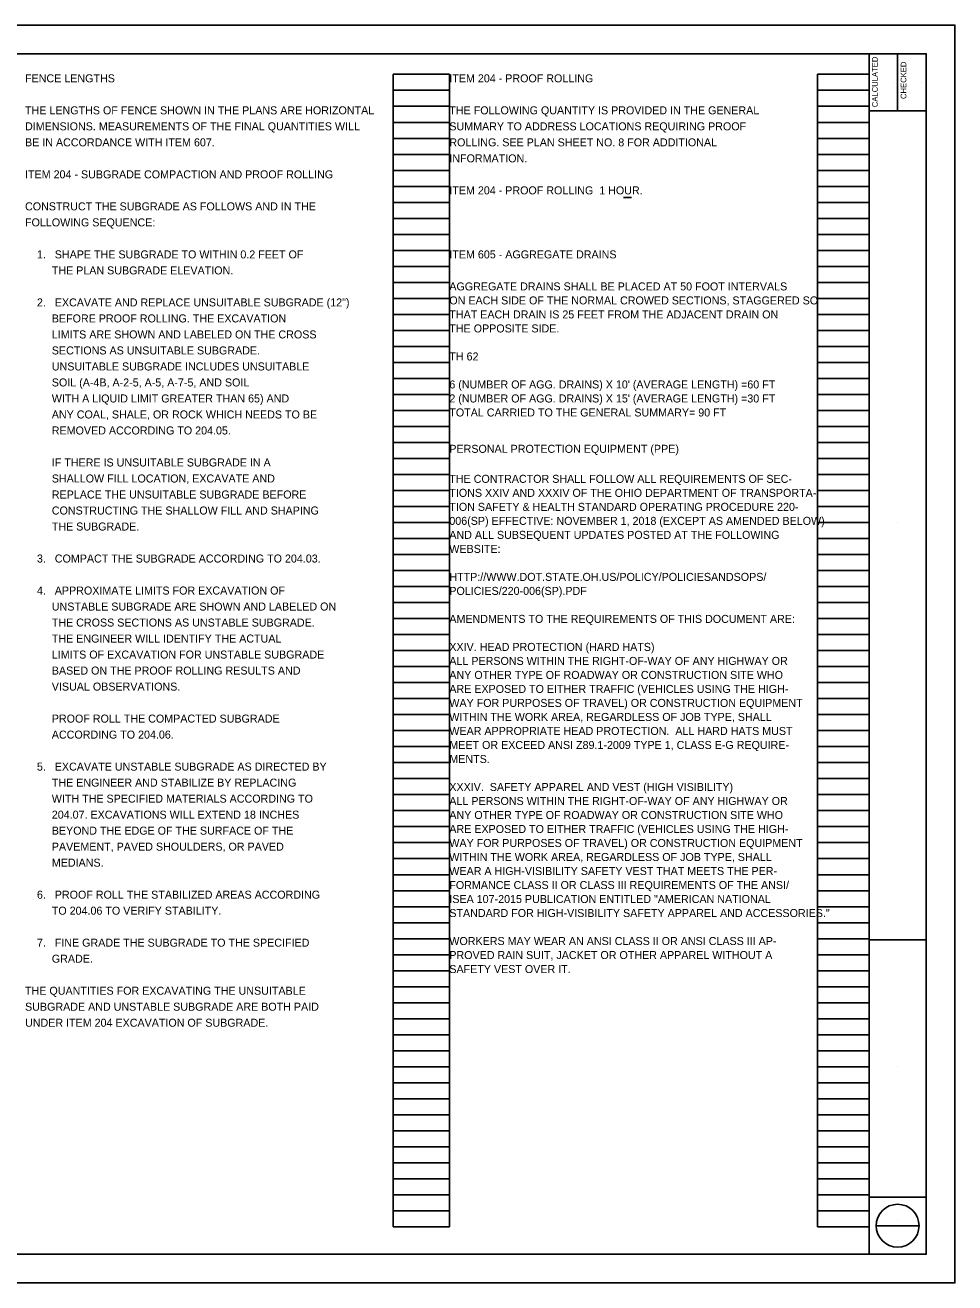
# Model space of a CAD drawing. Extents: x -14.3 to 49.6, y -18.9 to 35.3.
# Drawn here: x 17.74 to 34, y 0 to 22 of the extents above; entities that cross this region are included whole.
import ezdxf

# ---------------------------------------------------------------- set-up
doc = ezdxf.new("R2010")
doc.units = 0
for name, color, linetype in [('SH_Border', 7, 'Continuous'), ('SH_Cut_Line', 7, 'Continuous'), ('SH_Data', 7, 'Continuous'), ('SH_Text', 7, 'Continuous')]:
    doc.layers.add(name, color=color, linetype=linetype)

msp = doc.modelspace()

# ---------------------------------------------------------------- linework, layer by layer
at = {"layer": 'SH_Border'}
for p, q in [((32.5, 0.5), (32.5, 21.5)), ((33, 21.5), (33, 20.5)), ((32.5, 20.5), (33.5, 20.5)), ((32.5, 6), (33.5, 6)), ((32.5, 1.5), (33.5, 1.5))]:
    msp.add_line(p, q, dxfattribs=at)
msp.add_lwpolyline([(2, 21.5), (33.5, 21.5), (33.5, 0.5), (2, 0.5)], close=True, dxfattribs=at)
at = {"layer": 'SH_Cut_Line'}
msp.add_lwpolyline([(0, 0), (34, 0), (34, 22), (0, 22)], close=True, dxfattribs=at)
at = {"layer": 'SH_Data'}
for p, q in [((24.18, 0.98), (24.18, 21.14)), ((24.18, 21.14), (25.16, 21.14)), ((25.16, 0.98), (25.16, 21.14)), ((31.6, 0.98), (31.6, 21.14)), ((31.6, 21.14), (32.5, 21.14)), ((32.5, 0.98), (32.5, 21.14)), ((32.92, 21.004), (32.92, 21.004)), ((33.42, 21.004), (33.42, 21.004)), ((24.18, 20.86), (25.16, 20.86)), ((31.6, 20.86), (32.5, 20.86)), ((24.18, 20.58), (25.16, 20.58)), ((31.6, 20.58), (32.5, 20.58)), ((24.18, 20.3), (25.16, 20.3)), ((31.6, 20.3), (32.5, 20.3)), ((24.18, 20.02), (25.16, 20.02)), ((31.6, 20.02), (32.5, 20.02)), ((24.18, 19.74), (25.16, 19.74)), ((31.6, 19.74), (32.5, 19.74)), ((24.18, 19.46), (25.16, 19.46)), ((31.6, 19.46), (32.5, 19.46)), ((24.18, 19.18), (25.16, 19.18)), ((31.6, 19.18), (32.5, 19.18)), ((24.18, 18.9), (25.16, 18.9)), ((31.6, 18.9), (32.5, 18.9)), ((24.18, 18.62), (25.16, 18.62)), ((31.6, 18.62), (32.5, 18.62)), ((24.18, 18.34), (25.16, 18.34)), ((31.6, 18.34), (32.5, 18.34)), ((24.18, 18.06), (25.16, 18.06)), ((31.6, 18.06), (32.5, 18.06)), ((24.18, 17.78), (25.16, 17.78)), ((31.6, 17.78), (32.5, 17.78)), ((24.18, 17.5), (25.16, 17.5)), ((31.6, 17.5), (32.5, 17.5)), ((24.18, 17.22), (25.16, 17.22)), ((31.6, 17.22), (32.5, 17.22)), ((24.18, 16.94), (25.16, 16.94)), ((31.6, 16.94), (32.5, 16.94)), ((24.18, 16.66), (25.16, 16.66)), ((31.6, 16.66), (32.5, 16.66)), ((24.18, 16.38), (25.16, 16.38)), ((31.6, 16.38), (32.5, 16.38)), ((24.18, 16.1), (25.16, 16.1)), ((31.6, 16.1), (32.5, 16.1)), ((24.18, 15.82), (25.16, 15.82)), ((31.6, 15.82), (32.5, 15.82)), ((24.18, 15.54), (25.16, 15.54)), ((31.6, 15.54), (32.5, 15.54)), ((24.18, 15.26), (25.16, 15.26)), ((31.6, 15.26), (32.5, 15.26)), ((24.18, 14.98), (25.16, 14.98)), ((31.6, 14.98), (32.5, 14.98)), ((24.18, 14.7), (25.16, 14.7)), ((31.6, 14.7), (32.5, 14.7)), ((24.18, 14.42), (25.16, 14.42)), ((31.6, 14.42), (32.5, 14.42)), ((24.18, 14.14), (25.16, 14.14)), ((31.6, 14.14), (32.5, 14.14)), ((24.18, 13.86), (25.16, 13.86)), ((31.6, 13.86), (32.5, 13.86)), ((24.18, 13.58), (25.16, 13.58)), ((31.6, 13.58), (32.5, 13.58)), ((24.18, 13.3), (25.16, 13.3)), ((31.6, 13.3), (32.5, 13.3)), ((33, 13.292), (33, 13.292)), ((24.18, 13.02), (25.16, 13.02)), ((31.6, 13.02), (32.5, 13.02)), ((24.18, 12.74), (25.16, 12.74)), ((31.6, 12.74), (32.5, 12.74)), ((24.18, 12.46), (25.16, 12.46)), ((31.6, 12.46), (32.5, 12.46)), ((24.18, 12.18), (25.16, 12.18)), ((31.6, 12.18), (32.5, 12.18)), ((24.18, 11.9), (25.16, 11.9)), ((31.6, 11.9), (32.5, 11.9)), ((24.18, 11.62), (25.16, 11.62)), ((31.6, 11.62), (32.5, 11.62)), ((24.18, 11.34), (25.16, 11.34)), ((31.6, 11.34), (32.5, 11.34)), ((24.18, 11.06), (25.16, 11.06)), ((31.6, 11.06), (32.5, 11.06)), ((24.18, 10.78), (25.16, 10.78)), ((31.6, 10.78), (32.5, 10.78)), ((24.18, 10.5), (25.16, 10.5)), ((31.6, 10.5), (32.5, 10.5)), ((24.18, 10.22), (25.16, 10.22)), ((31.6, 10.22), (32.5, 10.22)), ((24.18, 9.94), (25.16, 9.94)), ((31.6, 9.94), (32.5, 9.94)), ((24.18, 9.66), (25.16, 9.66)), ((31.6, 9.66), (32.5, 9.66)), ((24.18, 9.38), (25.16, 9.38)), ((31.6, 9.38), (32.5, 9.38)), ((24.18, 9.1), (25.16, 9.1)), ((31.6, 9.1), (32.5, 9.1)), ((24.18, 8.82), (25.16, 8.82)), ((31.6, 8.82), (32.5, 8.82)), ((24.18, 8.54), (25.16, 8.54)), ((31.6, 8.54), (32.5, 8.54)), ((24.18, 8.26), (25.16, 8.26)), ((31.6, 8.26), (32.5, 8.26)), ((24.18, 7.98), (25.16, 7.98)), ((31.6, 7.98), (32.5, 7.98)), ((24.18, 7.7), (25.16, 7.7)), ((31.6, 7.7), (32.5, 7.7)), ((24.18, 7.42), (25.16, 7.42)), ((31.6, 7.42), (32.5, 7.42)), ((24.18, 7.14), (25.16, 7.14)), ((31.6, 7.14), (32.5, 7.14)), ((24.18, 6.86), (25.16, 6.86)), ((31.6, 6.86), (32.5, 6.86)), ((24.18, 6.58), (25.16, 6.58)), ((31.6, 6.58), (32.5, 6.58)), ((24.18, 6.3), (25.16, 6.3)), ((31.6, 6.3), (32.5, 6.3)), ((24.18, 6.02), (25.16, 6.02)), ((31.6, 6.02), (32.5, 6.02)), ((24.18, 5.74), (25.16, 5.74)), ((31.6, 5.74), (32.5, 5.74)), ((24.18, 5.46), (25.16, 5.46)), ((31.6, 5.46), (32.5, 5.46)), ((24.18, 5.18), (25.16, 5.18)), ((31.6, 5.18), (32.5, 5.18)), ((24.18, 4.9), (25.16, 4.9)), ((31.6, 4.9), (32.5, 4.9)), ((24.18, 4.62), (25.16, 4.62)), ((31.6, 4.62), (32.5, 4.62)), ((24.18, 4.34), (25.16, 4.34)), ((31.6, 4.34), (32.5, 4.34)), ((24.18, 4.06), (25.16, 4.06)), ((31.6, 4.06), (32.5, 4.06)), ((24.18, 3.78), (25.16, 3.78)), ((31.6, 3.78), (32.5, 3.78)), ((33, 3.792), (33, 3.792)), ((24.18, 3.5), (25.16, 3.5)), ((31.6, 3.5), (32.5, 3.5)), ((24.18, 3.22), (25.16, 3.22)), ((31.6, 3.22), (32.5, 3.22)), ((24.18, 2.94), (25.16, 2.94)), ((31.6, 2.94), (32.5, 2.94)), ((24.18, 2.66), (25.16, 2.66)), ((31.6, 2.66), (32.5, 2.66)), ((24.18, 2.38), (25.16, 2.38)), ((31.6, 2.38), (32.5, 2.38)), ((24.18, 2.1), (25.16, 2.1)), ((31.6, 2.1), (32.5, 2.1)), ((24.18, 1.82), (25.16, 1.82)), ((31.6, 1.82), (32.5, 1.82)), ((24.18, 1.54), (25.16, 1.54)), ((31.6, 1.54), (32.5, 1.54)), ((24.18, 1.26), (25.16, 1.26)), ((31.6, 1.26), (32.5, 1.26)), ((24.18, 0.98), (25.16, 0.98)), ((31.6, 0.98), (32.5, 0.98)), ((32.625, 1), (33.375, 1)), ((33, 1.085), (33, 1.085)), ((33, 0.745), (33, 0.745))]:
    msp.add_line(p, q, dxfattribs=at)
msp.add_circle((33, 1), 0.375, dxfattribs=at)
at = {"layer": 'SH_Text'}
msp.add_line((28.205, 18.988), (28.348, 18.988), dxfattribs=at)

# ---------------------------------------------------------------- texts
at = {"layer": 'SH_Data'}
for s, p in [('CALCULATED', (32.652, 20.565)), ('CHECKED', (33.152, 20.708))]:
    msp.add_text(s, height=0.1, rotation=90, dxfattribs=at).set_placement(p)
at = {"layer": 'SH_Text'}
for s, p in [('FENCE LENGTHS', (17.74, 21)), ('ITEM 204 - PROOF ROLLING', (25.16, 21)), ('THE LENGTHS OF FENCE SHOWN IN THE PLANS ARE HORIZONTAL', (17.74, 20.44)), ('THE FOLLOWING QUANTITY IS PROVIDED IN THE GENERAL', (25.16, 20.44)), ('DIMENSIONS. MEASUREMENTS OF THE FINAL QUANTITIES WILL', (17.74, 20.16)), ('SUMMARY TO ADDRESS LOCATIONS REQUIRING PROOF', (25.16, 20.16)), ('BE IN ACCORDANCE WITH ITEM 607.', (17.74, 19.88)), ('ROLLING. SEE PLAN SHEET NO. 8 FOR ADDITIONAL', (25.16, 19.88)), ('INFORMATION.', (25.16, 19.6)), ('ITEM 204 - SUBGRADE COMPACTION AND PROOF ROLLING', (17.74, 19.32)), ('ITEM 204 - PROOF ROLLING  1 HOUR.', (25.16, 19.04)), ('CONSTRUCT THE SUBGRADE AS FOLLOWS AND IN THE', (17.74, 18.76)), ('FOLLOWING SEQUENCE:', (17.74, 18.48)), ('    1.   SHAPE THE SUBGRADE TO WITHIN 0.2 FEET OF', (17.74, 17.92)), ('ITEM 605 - AGGREGATE DRAINS', (25.16, 17.92)), ('         THE PLAN SUBGRADE ELEVATION.', (17.74, 17.64)), ('AGGREGATE DRAINS SHALL BE PLACED AT 50 FOOT INTERVALS', (25.16, 17.36)), ('    2.   EXCAVATE AND REPLACE UNSUITABLE SUBGRADE (12")', (17.74, 17.08)), ('ON EACH SIDE OF THE NORMAL CROWED SECTIONS, STAGGERED SO', (25.16, 17.115)), ('         BEFORE PROOF ROLLING. THE EXCAVATION', (17.74, 16.8)), ('THAT EACH DRAIN IS 25 FEET FROM THE ADJACENT DRAIN ON', (25.16, 16.87)), ('THE OPPOSITE SIDE.', (25.16, 16.625)), ('         LIMITS ARE SHOWN AND LABELED ON THE CROSS', (17.74, 16.52)), ('         SECTIONS AS UNSUITABLE SUBGRADE.', (17.74, 16.24)), ('         UNSUITABLE SUBGRADE INCLUDES UNSUITABLE', (17.74, 15.96)), ('TH 62', (25.16, 16.135)), ('         SOIL (A-4B, A-2-5, A-5, A-7-5, AND SOIL', (17.74, 15.68)), ("6 (NUMBER OF AGG. DRAINS) X 10' (AVERAGE LENGTH) =60 FT", (25.16, 15.645)), ('         WITH A LIQUID LIMIT GREATER THAN 65) AND', (17.74, 15.4)), ("2 (NUMBER OF AGG. DRAINS) X 15' (AVERAGE LENGTH) =30 FT", (25.16, 15.4)), ('         ANY COAL, SHALE, OR ROCK WHICH NEEDS TO BE', (17.74, 15.12)), ('TOTAL CARRIED TO THE GENERAL SUMMARY= 90 FT', (25.16, 15.155)), ('         REMOVED ACCORDING TO 204.05.', (17.74, 14.84)), ('PERSONAL PROTECTION EQUIPMENT (PPE)', (25.16, 14.519)), ('         IF THERE IS UNSUITABLE SUBGRADE IN A', (17.74, 14.28)), ('         SHALLOW FILL LOCATION, EXCAVATE AND', (17.74, 14)), ('THE CONTRACTOR SHALL FOLLOW ALL REQUIREMENTS OF SEC-', (25.16, 13.994)), ('         REPLACE THE UNSUITABLE SUBGRADE BEFORE', (17.74, 13.72)), ('TIONS XXIV AND XXXIV OF THE OHIO DEPARTMENT OF TRANSPORTA-', (25.16, 13.749)), ('TION SAFETY & HEALTH STANDARD OPERATING PROCEDURE 220-', (25.16, 13.504)), ('         CONSTRUCTING THE SHALLOW FILL AND SHAPING', (17.74, 13.44)), ('         THE SUBGRADE.', (17.74, 13.16)), ('006(SP) EFFECTIVE: NOVEMBER 1, 2018 (EXCEPT AS AMENDED BELOW)', (25.16, 13.259)), ('AND ALL SUBSEQUENT UPDATES POSTED AT THE FOLLOWING', (25.16, 13.014)), ('WEBSITE:', (25.16, 12.769)), ('    3.   COMPACT THE SUBGRADE ACCORDING TO 204.03.', (17.74, 12.6)), ('HTTP://WWW.DOT.STATE.OH.US/POLICY/POLICIESANDSOPS/', (25.16, 12.279)), ('    4.   APPROXIMATE LIMITS FOR EXCAVATION OF', (17.74, 12.04)), ('POLICIES/220-006(SP).PDF', (25.16, 12.034)), ('         UNSTABLE SUBGRADE ARE SHOWN AND LABELED ON', (17.74, 11.76)), ('AMENDMENTS TO THE REQUIREMENTS OF THIS DOCUMENT ARE:', (25.16, 11.544)), ('         THE CROSS SECTIONS AS UNSTABLE SUBGRADE.', (17.74, 11.48)), ('         THE ENGINEER WILL IDENTIFY THE ACTUAL', (17.74, 11.2)), ('         LIMITS OF EXCAVATION FOR UNSTABLE SUBGRADE', (17.74, 10.92)), ('XXIV. HEAD PROTECTION (HARD HATS)', (25.16, 11.054)), ('         BASED ON THE PROOF ROLLING RESULTS AND', (17.74, 10.64)), ('ALL PERSONS WITHIN THE RIGHT-OF-WAY OF ANY HIGHWAY OR', (25.16, 10.809)), ('ANY OTHER TYPE OF ROADWAY OR CONSTRUCTION SITE WHO', (25.16, 10.564)), ('         VISUAL OBSERVATIONS.', (17.74, 10.36)), ('ARE EXPOSED TO EITHER TRAFFIC (VEHICLES USING THE HIGH-', (25.16, 10.319)), ('WAY FOR PURPOSES OF TRAVEL) OR CONSTRUCTION EQUIPMENT', (25.16, 10.074)), ('         PROOF ROLL THE COMPACTED SUBGRADE', (17.74, 9.8)), ('WITHIN THE WORK AREA, REGARDLESS OF JOB TYPE, SHALL', (25.16, 9.829)), ('WEAR APPROPRIATE HEAD PROTECTION.  ALL HARD HATS MUST', (25.16, 9.584)), ('         ACCORDING TO 204.06.', (17.74, 9.52)), ('MEET OR EXCEED ANSI Z89.1-2009 TYPE 1, CLASS E-G REQUIRE-', (25.16, 9.339)), ('    5.   EXCAVATE UNSTABLE SUBGRADE AS DIRECTED BY', (17.74, 8.96)), ('MENTS.', (25.16, 9.094)), ('         THE ENGINEER AND STABILIZE BY REPLACING', (17.74, 8.68)), ('XXXIV.  SAFETY APPAREL AND VEST (HIGH VISIBILITY)', (25.16, 8.604)), ('         WITH THE SPECIFIED MATERIALS ACCORDING TO', (17.74, 8.4)), ('ALL PERSONS WITHIN THE RIGHT-OF-WAY OF ANY HIGHWAY OR', (25.16, 8.359)), ('         204.07. EXCAVATIONS WILL EXTEND 18 INCHES', (17.74, 8.12)), ('ANY OTHER TYPE OF ROADWAY OR CONSTRUCTION SITE WHO', (25.16, 8.114)), ('         BEYOND THE EDGE OF THE SURFACE OF THE', (17.74, 7.84)), ('ARE EXPOSED TO EITHER TRAFFIC (VEHICLES USING THE HIGH-', (25.16, 7.869)), ('         PAVEMENT, PAVED SHOULDERS, OR PAVED', (17.74, 7.56)), ('WAY FOR PURPOSES OF TRAVEL) OR CONSTRUCTION EQUIPMENT', (25.16, 7.624)), ('WITHIN THE WORK AREA, REGARDLESS OF JOB TYPE, SHALL', (25.16, 7.379)), ('         MEDIANS.', (17.74, 7.28)), ('WEAR A HIGH-VISIBILITY SAFETY VEST THAT MEETS THE PER-', (25.16, 7.134)), ('    6.   PROOF ROLL THE STABILIZED AREAS ACCORDING', (17.74, 6.72)), ('FORMANCE CLASS II OR CLASS III REQUIREMENTS OF THE ANSI/', (25.16, 6.889)), ('ISEA 107-2015 PUBLICATION ENTITLED "AMERICAN NATIONAL', (25.16, 6.644)), ('         TO 204.06 TO VERIFY STABILITY.', (17.74, 6.44)), ('STANDARD FOR HIGH-VISIBILITY SAFETY APPAREL AND ACCESSORIES."', (25.16, 6.399)), ('    7.   FINE GRADE THE SUBGRADE TO THE SPECIFIED', (17.74, 5.88)), ('WORKERS MAY WEAR AN ANSI CLASS II OR ANSI CLASS III AP-', (25.16, 5.909)), ('         GRADE.', (17.74, 5.6)), ('PROVED RAIN SUIT, JACKET OR OTHER APPAREL WITHOUT A ', (25.16, 5.664)), ('SAFETY VEST OVER IT.  ', (25.16, 5.419)), ('THE QUANTITIES FOR EXCAVATING THE UNSUITABLE', (17.74, 5.04)), ('SUBGRADE AND UNSTABLE SUBGRADE ARE BOTH PAID', (17.74, 4.76)), ('UNDER ITEM 204 EXCAVATION OF SUBGRADE.', (17.74, 4.48))]:
    msp.add_text(s, height=0.14, dxfattribs=at).set_placement(p)

doc.saveas('drawing.dxf')
